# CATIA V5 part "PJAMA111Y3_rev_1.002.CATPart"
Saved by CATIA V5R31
Part number: JAMA111Y3
Revision: 1
Nomenclature: BRACE_R_LH
Source: Unknown
Property "部品番号(A社)": "JAMA111Y3"
Property "部品名称(A社)": "BRACE_R_LH"
Property "Version(A社)": "1"
Property "材質(A社)": "SPCN2"
Property "板厚": "0.9"
Bounding box of the stored display mesh (mm): x 4183.201 to 4343.432, y -559.056 to -289.334, z 678 to 858
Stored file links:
  \\solize.local\damia\dept\DDE_Design\10_order\2305701_JAMA_変換検証STEP3_お手本モデル作成\work\02_マツダ_板金\10_CATIA_V5\231211\PJAMA111Y3_rev_1.002.CATPart
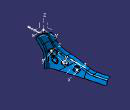
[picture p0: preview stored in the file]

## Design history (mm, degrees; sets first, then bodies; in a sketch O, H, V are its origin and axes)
TTRSSet1
f4a2d38f3ddc11d3a929006094b99c4b_11 "CATTPSSet"
Set1
  DatumSurface1 "OPEN_SHELL #623"
Set2
  DatumCurve1
  Point1: stored without definition
  Point2: stored without definition
  AxisSystem1: origin (4240, -421, 701.5), X (0.4072, -0.386, -0.8278), Y (0.1462, -0.8671, 0.4762), Z (-0.9016, -0.315, -0.2966)
  AxisSystem2: origin (4277.5, -523, 760), X (-0.1462, 0.8671, -0.4762), Y (0.4072, -0.386, -0.8278), Z (-0.9016, -0.315, -0.2966)
  DatumCurve2
  DatumCurve3
  AxisSystem3: origin (4294.2416, -520.4956, 830), X (0.7496, -0.6619, 0), Y (-0.6243, -0.7071, 0.332), Z (-0.2197, -0.2488, -0.9433)
  Sketch1 on XY plane of AxisSystem3, origin (4294.2416, -520.4956, 830), H (-0.7496, 0.6619, 0), V (-0.6243, -0.7071, 0.332)
    point P1 (-17.6099, 23.0492)
    line L1 (-17.6099, 23.0492) -> (-17.6099, 38.0492)
    point P2 (-17.6099, 38.0492)
    line L2 (-17.6099, 38.0492) -> (-18.9497, 33.0493)
    construction line L3 (-18.9497, 33.0493) -> (-16.2702, 33.0493)
    line L4 (-16.2702, 33.0493) -> (-17.6099, 38.0492)
    point P5 (-17.6099, 38.0492)
    angle L2 L4 = 30
    distance L3 P1 = 10
    distance P2 L3 = 5
    vertical: L1 V
    horizontal: L3 H
    coincidence: P5 L2, P5 L1
    symmetry: L2 L4 L1
  AxisSystem4: origin (4283.6867, -559.056, 842.6311), X (1, 0, 0), Y (0, 1, 0), Z (0, 0, 1)
Body1 (main body)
